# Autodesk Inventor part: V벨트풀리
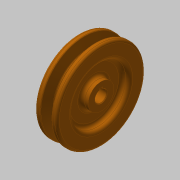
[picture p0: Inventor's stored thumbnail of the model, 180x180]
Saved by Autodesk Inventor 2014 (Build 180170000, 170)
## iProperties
Created: 2015-11
Part Number: V벨트풀리
Material: 알루미늄 6061
Document SubType Name: Modeling
Designer: mduedu
Density: 1 g/cm^3
Appearance: 주황색
Author: mduedu
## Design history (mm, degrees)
sketch "스케치1"
  geometry: L1 (-9.5, 0)-(9.5, 0); L2 (0, 0)-(0, 37.7); L3 (-4.825, 37.7)-(-9.5, 37.7); L4 (-9.5, 37.7)-(-9.5, 0); L5 (0, 28.7)-(-2.074, 28.7); L6 (-2.074, 28.7)-(-4.825, 37.7); L7 (4.825, 37.7)-(9.5, 37.7); L8 (9.5, 37.7)-(9.5, 0); L9 (0, 28.7)-(2.074, 28.7); L10 (2.074, 28.7)-(4.825, 37.7); L11 (-9.5, 35)-(9.5, 35); 3 further points
  constraints: 22 end point, 7 point on line, 4 perpendicular, 3 symmetric about line, 1 coincident, 1 horizontal, 1 horizontal alignment, 1 midpoint, 1 vertical
  dimensions: "d0" = 19 distance of L1.start L1.end; "d2" = 75.4 diameter of L2.end L1 (derived); "d3" = 34 deg angle of L10 L6; "d4" = 6.3 distance between parallel lines of L11 L9; "d5" = 2.7 distance between parallel lines of L7 L11; "d6" = 8 distance of point (4, 35) point (-4, 35); "d7" = 70 diameter of L11 L1
revolve "회전1" sketch "스케치1" stored, may be unused: angle "d8" = 90 deg
sketch "스케치2"
  geometry: C1 r 24 at (0, 0); C2 r 11 at (0, 0); 1 further point
  constraints: 2 centre point, 2 coincident
  dimensions: "d9" = 48 diameter of C1; "d10" = 22 diameter of C2
extrude "돌출1" cut sketch "스케치2" distance "d11" = 6; taper "d12" = 0 deg
fillet "모깎기1" dims "d13" = 3
fillet "모깎기2" dims "d14" = 3
fillet "모깎기3" dims "d15" = 1, "d16" = 0.5, "d17" = 2
hole "구멍1" diameter "d20" = 10; stored, may be unused: countersink angle "d24" = 90 deg, drill point angle "d26" = 118 deg; dims "d18" = 10, "d19" = 10, "d21" = 6, "d22" = 4, "d23" = 2, "d25" = 8
sketch "스케치3"
  geometry: L1 (-1.5, 0)-(1.5, 0); L2 (1.5, 0)-(1.5, 6.4); L3 (1.5, 6.4)-(-1.5, 6.4); L4 (-1.5, 6.4)-(-1.5, 0); 2 further points
  constraints: 8 end point, 2 parallel, 1 coincident, 1 horizontal, 1 midpoint, 1 perpendicular
  dimensions: "d27" = 3 distance of L2.end L3.end; "d29" = 6.4 distance of L3.end L1.start
extrude "돌출2" cut sketch "스케치3" stored distance "d30" = 6; taper "d31" = 0 deg
chamfer "모따기1" distance "d32" = 0.5; stored, may be unused: second distance "d33" = 2, angle "d34" = 45 deg
node "솔리드1"
mirror "대칭1"
